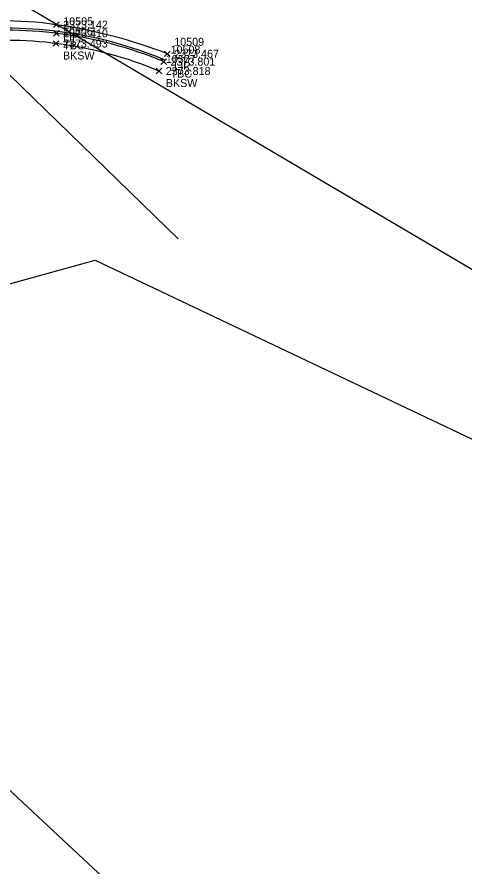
# Model space of a CAD drawing. Extents: x 2377639 to 2379738, y 729875 to 732734.
# Drawn here: x 2379345.6 to 2379457.4, y 731268.8 to 731481.1 of the extents above; entities that cross this region are included whole.
import ezdxf

# ---------------------------------------------------------------- set-up
doc = ezdxf.new("R2010")
doc.units = 0
for name, color, linetype in [('TOPO_CURBGTR_Back-of-Curb', 7, 'Continuous'), ('TOPO_CURBGTR_Face-of-Curb', 7, 'Continuous'), ('TOPO_CURBGTR_Lip-of-Gutter', 7, 'Continuous'), ('TOPO_DATA_Elevations', 7, 'Continuous'), ('TOPO_SAN_Plastic-Pipe', 7, 'Continuous'), ('TOPO_STORM_Rigid-Plastic-Pipe', 7, 'Continuous'), ('TOPO_SW_Back', 7, 'Continuous'), ('TOPO_TELE_Underground-FO-Cable', 7, 'Continuous'), ('TRAF_PAVEMARK_White_8-IN', 7, 'Continuous')]:
    doc.layers.add(name, color=color, linetype=linetype)

msp = doc.modelspace()

# ---------------------------------------------------------------- linework, layer by layer
at = {"layer": 'TOPO_CURBGTR_Back-of-Curb'}
msp.add_arc((2379342.87, 731375.1), 102.65, 67.4697, 97.6381, dxfattribs=at)
at = {"layer": 'TOPO_CURBGTR_Face-of-Curb'}
msp.add_arc((2379342.87, 731375.1), 103.15, 67.4697, 97.6413, dxfattribs=at)
at = {"layer": 'TOPO_CURBGTR_Lip-of-Gutter'}
for centre, radius, start, end in [((2379342.13, 731386.38), 93.7, 81.8687, 116.0868), ((2379337.63, 731354.87), 125.52, 68.7522, 81.8687)]:
    msp.add_arc(centre, radius, start, end, dxfattribs=at)
at = {"layer": 'TOPO_DATA_Elevations'}
for p, q in [((2379354.68, 731478.43), (2379356.09, 731479.84)), ((2379354.68, 731479.84), (2379356.09, 731478.43)), ((2379354.69, 731476.28), (2379356.11, 731477.69)), ((2379354.69, 731477.69), (2379356.11, 731476.28)), ((2379354.63, 731473.74), (2379356.05, 731475.15)), ((2379354.63, 731475.15), (2379356.05, 731473.74)), ((2379382.41, 731471.16), (2379383.83, 731472.57)), ((2379382.41, 731472.57), (2379383.83, 731471.16)), ((2379381.49, 731469.21), (2379382.91, 731470.62)), ((2379381.49, 731470.62), (2379382.91, 731469.21)), ((2379380.3, 731466.86), (2379381.72, 731468.28)), ((2379380.3, 731468.28), (2379381.72, 731466.86))]:
    msp.add_line(p, q, dxfattribs=at)
at = {"layer": 'TOPO_SAN_Plastic-Pipe'}
msp.add_line((2379447.29, 731191.48), (2379157.76, 731461.12), dxfattribs=at)
at = {"layer": 'TOPO_STORM_Rigid-Plastic-Pipe'}
msp.add_line((2379735.51, 731254.78), (2379320.96, 731499.59), dxfattribs=at)
at = {"layer": 'TOPO_SW_Back'}
msp.add_arc((2379343.04, 731377.19), 98.03, 67.2148, 97.6204, dxfattribs=at)
at = {"layer": 'TOPO_TELE_Underground-FO-Cable'}
for p, q in [((2379385.77, 731425.66), (2379134.23, 731670.17)), ((2379215.41, 731379.11), (2379365.1, 731420.37)), ((2379365.1, 731420.37), (2379627.88, 731295.35))]:
    msp.add_line(p, q, dxfattribs=at)
at = {"layer": 'TRAF_PAVEMARK_White_8-IN'}
msp.add_arc((2379344.91, 731379.53), 114.56, 69.8504, 118.7174, dxfattribs=at)

# ---------------------------------------------------------------- texts
at = {"layer": 'TOPO_DATA_Elevations'}
for s, p in [('2373.142', (2379357.09, 731478.14)), ('10505', (2379357.11, 731478.98)), ('2373.410', (2379357.11, 731475.98)), ('10506', (2379357.05, 731476.44)), ('2373.493', (2379357.05, 731473.44)), ('LIP', (2379357.09, 731475.14)), ('10509', (2379384.83, 731473.87)), ('TBC', (2379357.11, 731472.98)), ('10508', (2379383.91, 731471.92)), ('BKSW', (2379357.05, 731470.44)), ('10507', (2379382.72, 731469.57)), ('2373.801', (2379383.91, 731468.92)), ('2373.467', (2379384.83, 731470.87)), ('LIP', (2379384.83, 731467.87)), ('2373.818', (2379382.72, 731466.57)), ('TBC', (2379383.91, 731465.92)), ('BKSW', (2379382.72, 731463.57))]:
    msp.add_text(s, height=2, dxfattribs=at).set_placement(p)

doc.saveas('drawing.dxf')
